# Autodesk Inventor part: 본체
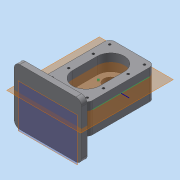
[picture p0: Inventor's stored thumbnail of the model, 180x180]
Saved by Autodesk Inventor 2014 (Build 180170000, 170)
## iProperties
Created: 2026-10
Part Number: 본체
Material: 일반
Document SubType Name: Modeling
Designer: dg
Density: 1 g/cm^3
Appearance: 기본값
Author: dg
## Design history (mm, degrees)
sketch "스케치1"
  geometry: L1 (-40, 60)-(40, 60); L2 (40, 60)-(40, -60); L3 (40, -60)-(-40, -60); L4 (-40, -60)-(-40, 60); 3 further points
  constraints: 8 end point, 2 midpoint, 2 parallel, 1 horizontal, 1 horizontal alignment, 1 perpendicular, 1 vertical alignment
  dimensions: "d0" = 80 distance of L1.start L1.end; "d1" = 120 distance of L3.end L1.start
extrude "돌출1" new body sketch "스케치1" stored distance "d2" = 53; taper "d3" = 0 deg
sketch "스케치2"
  geometry: L1 (-40, 60)-(-40, -60) reference; L2 (0, 22)-(0, -22); L3 (-24, 22)-(-24, -22); L4 (24, -22)-(24, 22); A1 r 24 centre (0, 22) between (24, 22) and (-24, 22); A2 r 24 centre (0, -22) between (-24, -22) and (24, -22); 2 further points
  constraints: 8 end point, 4 point on circle, 4 tangent, 2 centre point, 2 coincident, 2 parallel, 1 midpoint
  dimensions: "d4" = 44 distance of L2.end L2.start; "d6" = 48 distance between parallel lines of L4 L3
extrude "돌출2" cut sketch "스케치2" distance "d7" = 29; taper "d8" = 0 deg
fillet "모깎기1" dims "d9" = 9
sketch "스케치5"
  geometry: C1 r 19 at (0, 22); 1 further point
  constraints: 1 centre point, 1 vertical alignment
  dimensions: "d13" = 22 distance of point (0, 0) C1.centre; "d14" = 38 diameter of C1
extrude "돌출3" join sketch "스케치5" distance "d15" = 17; taper "d16" = 0 deg
sketch "스케치6"
  geometry: L1 (22, -2.623)-(22, -43.5); L2 (3, -43.5)-(41, -43.5) reference; L3 (22, -2.5)-(46, -2.5) reference; L4 (34.5, -2.5)-(34.5, -17.5); L5 (34.5, -17.5)-(30.5, -17.5); L6 (30.5, -17.5)-(30.5, -36.2); L7 (30.5, -36.2)-(35.596, -36.2); L8 (35.596, -36.2)-(35.596, -42.8); L9 (35.596, -42.8)-(36, -43.5); L10 (-22, -2.623)-(-22, -17.5); L11 (-22, -17.5)-(-9.5, -17.5); L12 (-9.5, -17.5)-(-9.5, -2.5); L13 (-22, -2.5)-(22, -2.5) reference; L14 (34.5, -2.5)-(22, -2.5); L15 (36, -43.5)-(22, -43.5); L16 (-9.5, -2.5)-(-22, -2.5); L17 (22, -2.5)-(22, -43.5); L18 (-22, -2.5)-(-22, -17.5); 1 further point
  constraints: 30 end point, 5 parallel, 3 collinear, 3 point on line, 2 perpendicular, 1 horizontal, 1 midpoint, 1 vertical
  dimensions: "d17" = 22 distance from line of point (0, 0) L1; "d18" = 7.3 distance from line of L9.end L7; "d19" = 30 deg angle of L8 L9; "d20" = 15 distance of L4.start L4.end; "d21" = 25 diameter of L4 L1; "d22" = 17 diameter of L6 L1; "d24" = 28 diameter of L9.end L1; "d25" = 0.7 vertical distance of L8.end L9.end; "d26" = 22 distance from line of L10 point (0, 0); "d27" = 25 diameter of L12 L10; "d28" = 15 distance of L11.end L12.end
revolve "회전1" stored, may be unused: angle "d29" = 90 deg
revolve "회전2" stored, may be unused: angle "d30" = 90 deg
node "작업 평면1"
sketch "스케치7"
  geometry: L1 (-60, 56.5)-(60, 56.5); L2 (60, 56.5)-(60, -43.5); L3 (-60, -43.5)-(-60, 56.5); L4 (-19, -43.5)-(19, -43.5) reference; L5 (-60, -43.5)-(60, -43.5); 3 further points
  constraints: 8 end point, 3 midpoint, 2 parallel, 1 collinear, 1 horizontal, 1 perpendicular, 1 vertical alignment
  dimensions: "d34" = 100 distance of L3.start L1.start; "d35" = 120 distance between parallel lines of L2 L3
extrude "돌출4" join sketch "스케치7" distance "d36" = 10; taper "d37" = 0 deg
sketch "스케치8"
  geometry: L1 (-80, -43.5)-(-80, 56.5) reference; L2 (-80, 26.5)-(-46, 6.87); L3 (-46, -6.87)-(-80, -26.5); L4 (-46, 6.87)-(-46, -6.87); L5 (-46, 26.5)-(-46, -2.5) reference; 2 further points
  constraints: 6 end point, 3 point on line, 1 midpoint, 1 parallel
  dimensions: "d38" = 17 distance of L1.start L3.end; "d39" = 53 distance of L3.end L2.start; "d40" = 60 deg angle of L1 L2; "d41" = 60 deg angle of L1 L3
extrude "돌출5" join sketch "스케치8" stored distance "d42" = 48; taper "d43" = 0 deg
fillet "모깎기2" dims "d49" = 10
sketch "스케치10"
  geometry: A1 r 9 centre (31, 51) between (40, 51) and (31, 60) reference; A2 r 9 centre (-31, 51) between (-31, 60) and (-40, 51) reference; 5 further points
  constraints: 2 coincident, 2 vertical alignment, 1 horizontal alignment
  dimensions: "d50" = 29 distance of point (-31, 22) point (-31, 51)
hole "구멍1" sketch "스케치10" at (-31, 51), (-31, 22), (31, 51), (31, 22) diameter "d51" = 4.134; stored, may be unused: countersink angle "d55" = 82 deg, drill point angle "d57" = 118 deg; dims "d52" = 10, "d53" = 3.023, "d54" = 2, "d56" = 12
node "작업 평면2"
sketch "스케치11"
  geometry: L1 (-40, 51)-(-40, -51) reference; L2 (40, -51)-(40, 51) reference; L3 (-40, 0)-(-53.57, 0); L4 (40, 0)-(54.728, 0); 1 further point
  constraints: 4 end point, 2 midpoint, 1 collinear, 1 perpendicular
node "솔리드1"
mirror "대칭1"
other parameters: "d58" = 12.5
